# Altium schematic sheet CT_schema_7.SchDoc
size 287 x 160 mm
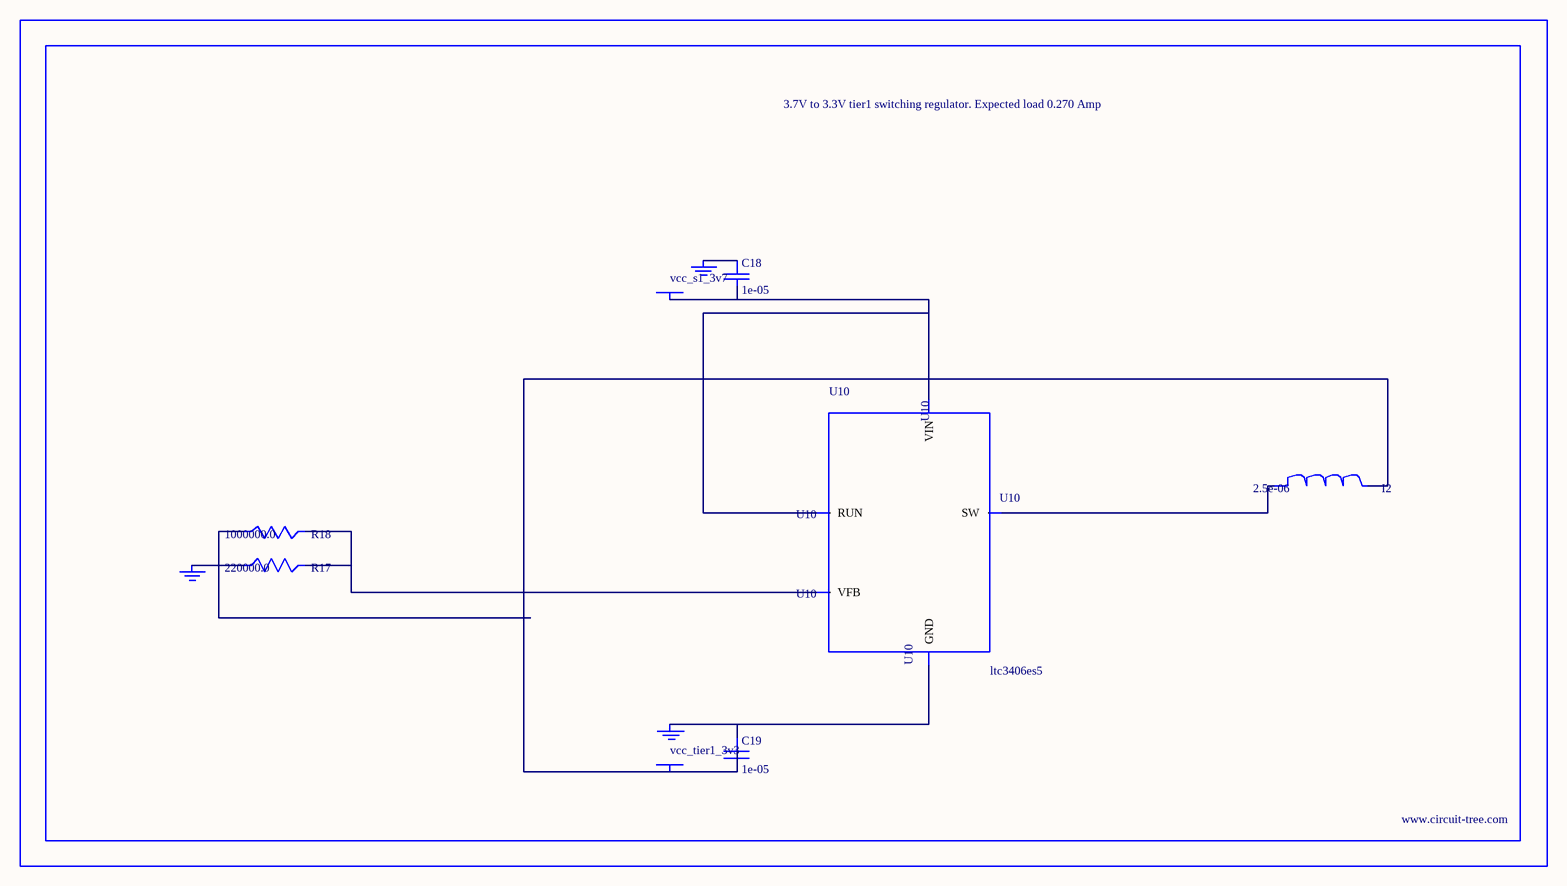
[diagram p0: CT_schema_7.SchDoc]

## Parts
BORDER6  (no value)
C18  1e-05  [C0805]
C19  1e-05  [C0805]
GND_INSTANCE_6_0  (no value)
GND_INSTANCE_6_1  (no value)
GND_INSTANCE_6_2  (no value)
I2  2.5e-06  [DR1040]
POWER_INSTANCE_6_0  vcc_tier1_3v3
POWER_INSTANCE_6_1  vcc_s1_3v7
R17  220000.0  [R0603]
R18  1000000.0  [R0603]
U10  ltc3406es5  [TSOT-23-5]

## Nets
NetC18_1: C18.1 GND_INSTANCE_6_1.0(GND)
NetC18_2: C18.2 POWER_INSTANCE_6_1.0(PWR) U10.1(RUN) U10.4(VIN)
NetC19_1: C19.1 GND_INSTANCE_6_0.0(GND) U10.2(GND)
NetC19_2: C19.2 I2.2 POWER_INSTANCE_6_0.0(PWR) R18.1
NetGND_INSTANCE_6_2_0: GND_INSTANCE_6_2.0(GND) R17.1
NetI2_1: I2.1 U10.3(SW)
NetR17_2: R17.2 R18.2 U10.5(VFB)

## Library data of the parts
BORDER6 = BORDER_PAGE6
C18 C19 = C0805C106K8RACTU
GND_INSTANCE_6_0-GND_INSTANCE_6_2 = GND
I2 = DR1040-2R5-R
POWER_INSTANCE_6_0 POWER_INSTANCE_6_1 = PWR
R17 = RC0603JR-07220KL
R18 = RC0603JR-071ML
